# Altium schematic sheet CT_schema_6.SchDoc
size 283 x 147 mm
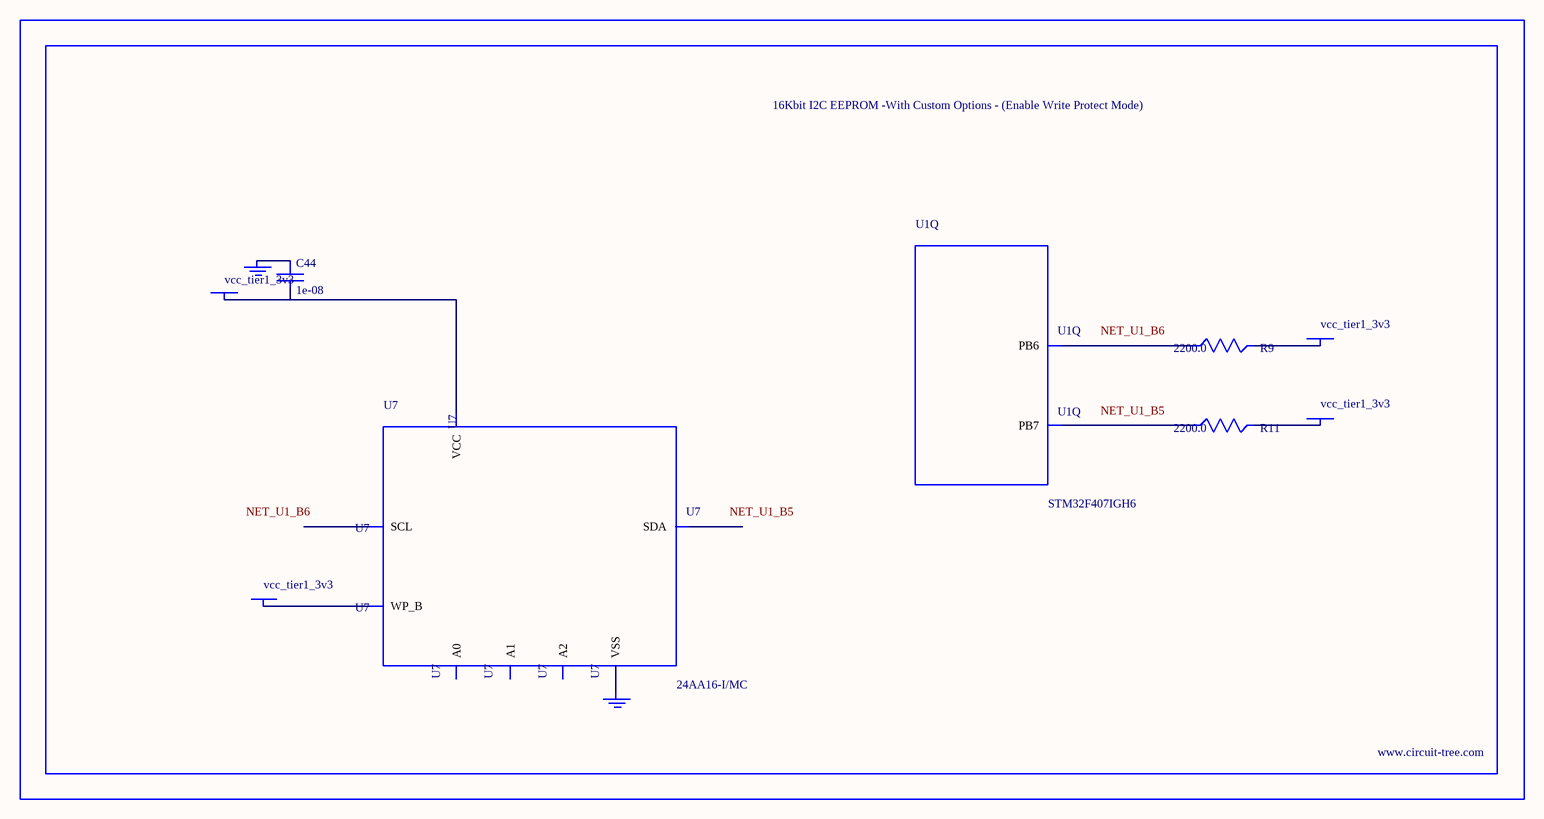
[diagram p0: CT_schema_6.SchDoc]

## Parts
BORDER5  (no value)
C44  1e-08  [C0402]
GND_INSTANCE_5_0  (no value)
GND_INSTANCE_5_1  (no value)
POWER_INSTANCE_5_0  vcc_tier1_3v3
POWER_INSTANCE_5_1  vcc_tier1_3v3
POWER_INSTANCE_5_2  vcc_tier1_3v3
POWER_INSTANCE_5_3  vcc_tier1_3v3
R9  2200.0  [R0603]
R11  2200.0  [R0603]
U1  STM32F407IGH6  [UFBGA176]  (part Q of 18)
U7  24AA16-I/MC  [TDFN-8/6MM]

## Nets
NetC44_1: C44.1 GND_INSTANCE_5_0.0(GND)
NetC44_2: C44.2 POWER_INSTANCE_5_1.0(PWR) U7.8(VCC)
NetGND_INSTANCE_5_1_0: GND_INSTANCE_5_1.0(GND) U7.4(VSS)
NetPOWER_INSTANCE_5_0_0: POWER_INSTANCE_5_0.0(PWR) U7.7(WP_B)
NetPOWER_INSTANCE_5_2_0: POWER_INSTANCE_5_2.0(PWR) R9.2
NetPOWER_INSTANCE_5_3_0: POWER_INSTANCE_5_3.0(PWR) R11.2
NetR9_1: R9.1 U1.B6(PB6)
NetR11_1: R11.1 U1.B5(PB7)

Not connected (* = marked no-connect by the designer): U7 1(A0) 2(A1) 3(A2) 5(SDA) 6(SCL)

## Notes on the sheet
- Labels drawn without touching a wire or pin: NET_U1_B5, NET_U1_B6

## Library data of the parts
BORDER5 = BORDER_PAGE5
C44 = C0402C103K3RAC
GND_INSTANCE_5_0 GND_INSTANCE_5_1 = GND
POWER_INSTANCE_5_0-POWER_INSTANCE_5_3 = PWR
R9 R11 = RC0603JR-072K2L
